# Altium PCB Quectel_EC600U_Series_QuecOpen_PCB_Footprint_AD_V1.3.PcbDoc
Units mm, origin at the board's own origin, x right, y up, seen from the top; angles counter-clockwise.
Board outline 152.4 x 101.6 mm, 2 copper layers (Top Layer, Bottom Layer); 1 components, 0 nets, 148 pads, 0 vias.
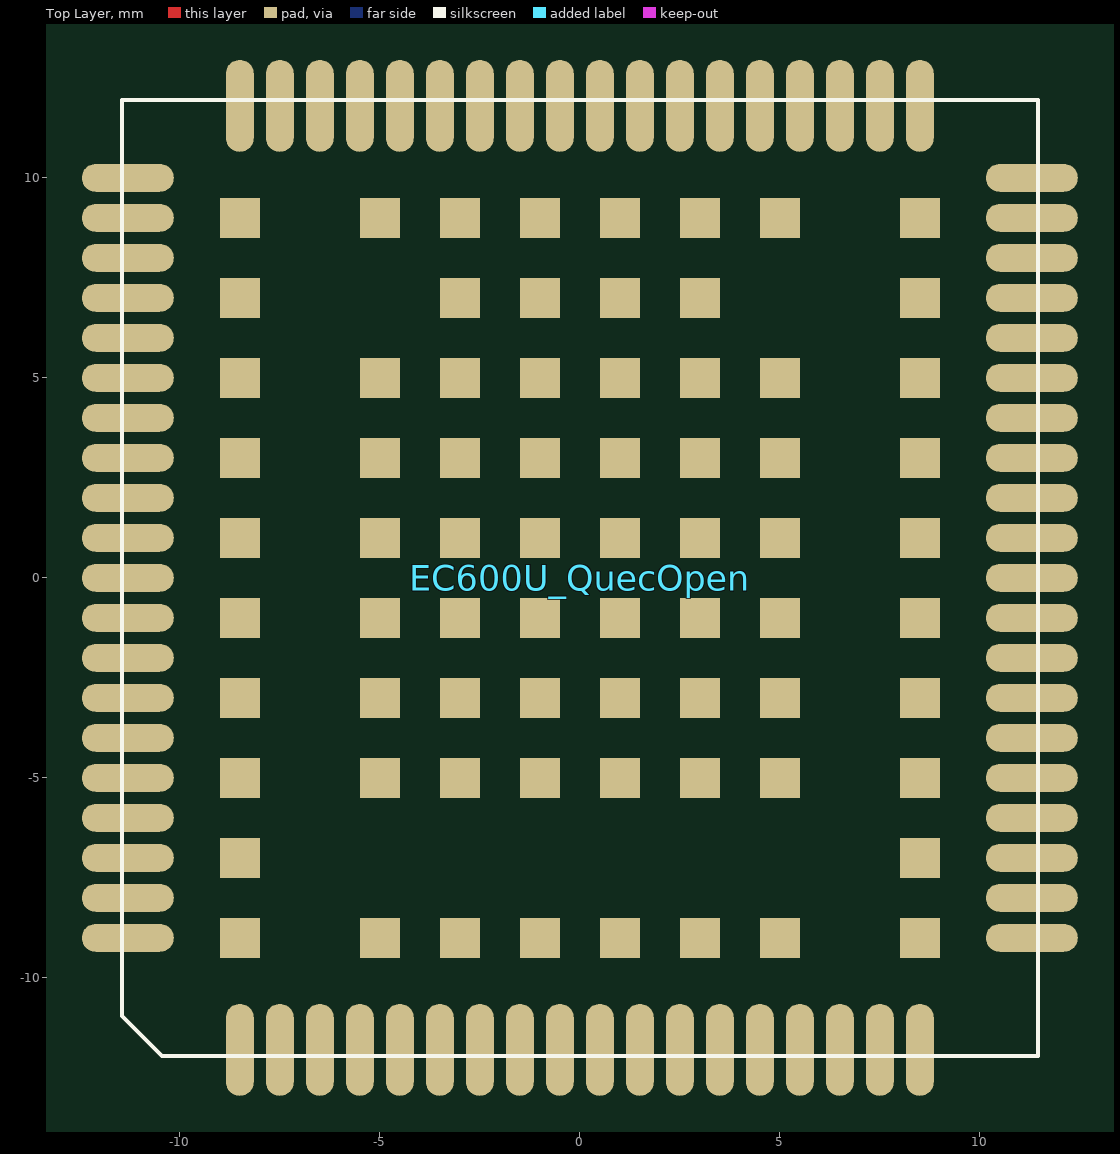
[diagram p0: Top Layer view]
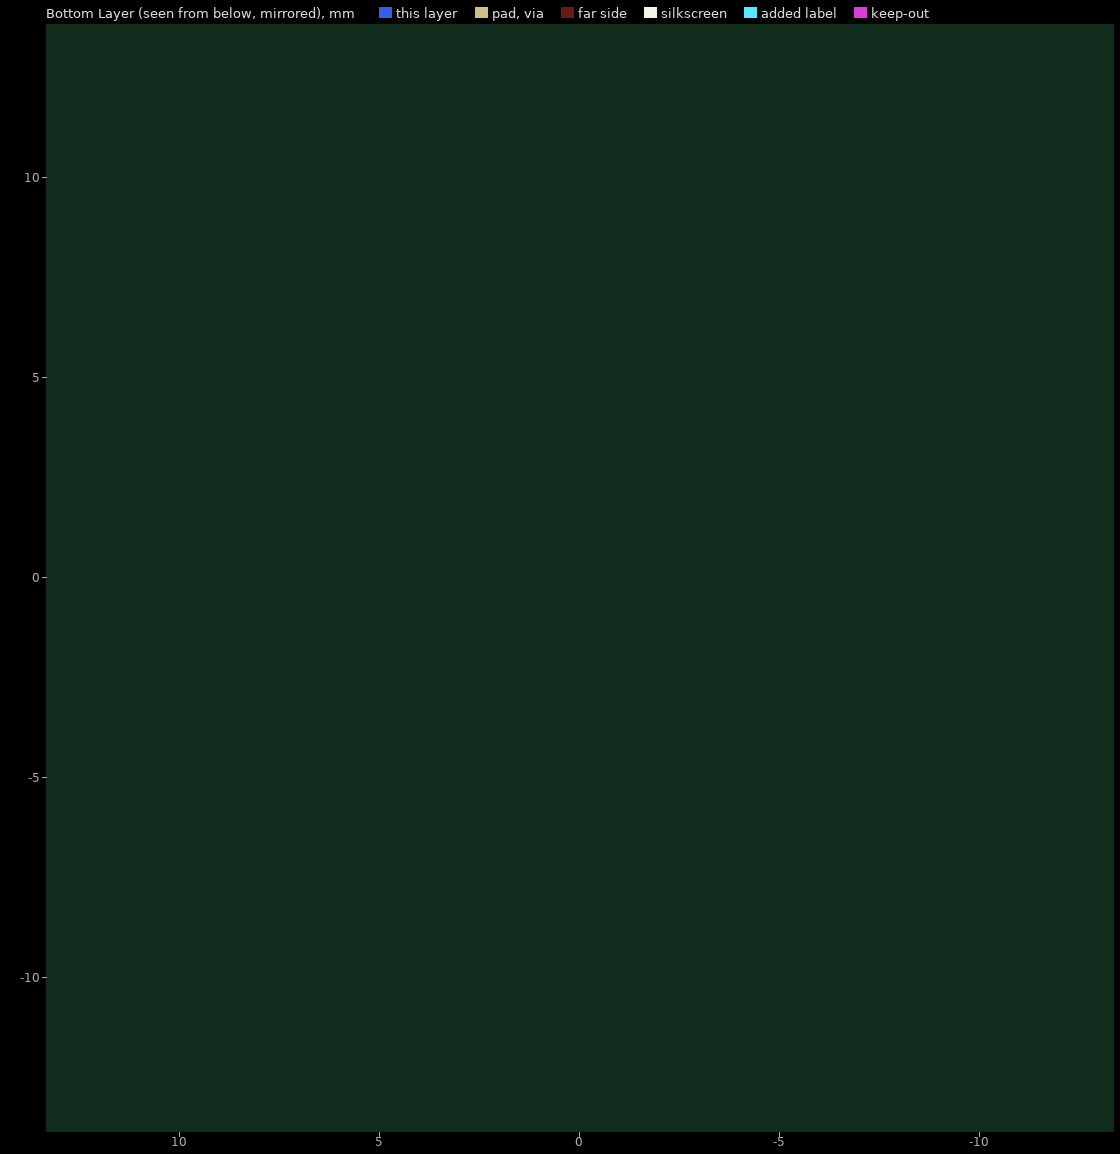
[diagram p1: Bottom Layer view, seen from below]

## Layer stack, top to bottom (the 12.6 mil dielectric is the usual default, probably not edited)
Top Solder: solder mask 0.0102, Solder Resist, Dk 3.5
Top Layer: signal copper 0.0356
Dielectric1: dielectric 0.32, FR-4, Dk 4.8
Bottom Layer: signal copper 0.0356
Bottom Solder: solder mask 0.0102, Solder Resist, Dk 3.5

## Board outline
-80.899,-52.07 71.501,-52.07 71.501,49.53 -80.899,49.53

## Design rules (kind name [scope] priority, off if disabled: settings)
Clearance [All] p1: gap=0.254
PolygonConnect [All] p1: connectstyle=Relief reliefconductorwidth=0.254 reliefentries=4 polygonreliefangle="90 Angle" airgapwidth=0.254
RoutingVias [All] p1: holewidth=0.711 width=1.27 viastyle="Through Hole" minholewidth=0.711 minwidth=1.27 maxholewidth=0.711 maxwidth=1.27
SolderMaskExpansion [All] p1: expansion=0.102
Width [All] p1: maxlimit=0.254 minlimit=0.254 preferedwidth=0.254
30 further rules are at their usual default settings.

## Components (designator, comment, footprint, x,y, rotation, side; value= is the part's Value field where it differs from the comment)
EC600U_QuecOpen "Comment" EC600U_QuecOpen 0,0 r0 top

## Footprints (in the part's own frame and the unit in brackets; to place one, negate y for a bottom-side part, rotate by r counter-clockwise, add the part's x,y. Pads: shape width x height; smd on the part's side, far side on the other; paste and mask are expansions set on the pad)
EC600U_QuecOpen [mm] "EC600U_QuecOpen Module LCC76PIN LGA72PIN H2.4mm RO"
  oval 0.7x2.3 smd mask+0.05: 1(-8.5,-11.8) 2(-7.5,-11.8) 3(-6.5,-11.8) 4(-5.5,-11.8) 5(-4.5,-11.8) 6(-3.5,-11.8) 7(-2.5,-11.8) 8(-1.5,-11.8) 9(-0.5,-11.8) 10(0.5,-11.8) 11(1.5,-11.8) 12(2.5,-11.8) 13(3.5,-11.8) 14(4.5,-11.8) 15(5.5,-11.8) 16(6.5,-11.8) 17(7.5,-11.8) 18(8.5,-11.8) 39(8.5,11.8) 40(7.5,11.8) 41(6.5,11.8) 42(5.5,11.8) 43(4.5,11.8) 44(3.5,11.8) 45(2.5,11.8) 46(1.5,11.8) 47(0.5,11.8) 48(-0.5,11.8) 49(-1.5,11.8) 50(-2.5,11.8) 51(-3.5,11.8) 52(-4.5,11.8) 53(-5.5,11.8) 54(-6.5,11.8) 55(-7.5,11.8) 56(-8.5,11.8)
  oval 2.3x0.7 smd mask+0.05: 19(11.3,-9) 20(11.3,-8) 21(11.3,-7) 22(11.3,-6) 23(11.3,-5) 24(11.3,-4) 25(11.3,-3) 26(11.3,-2) 27(11.3,-1) 28(11.3,0) 29(11.3,1) 30(11.3,2) 31(11.3,3) 32(11.3,4) 33(11.3,5) 34(11.3,6) 35(11.3,7) 36(11.3,8) 37(11.3,9) 38(11.3,10) 57(-11.3,10) 58(-11.3,9) 59(-11.3,8) 60(-11.3,7) 61(-11.3,6) 62(-11.3,5) 63(-11.3,4) 64(-11.3,3) 65(-11.3,2) 66(-11.3,1) 67(-11.3,0) 68(-11.3,-1) 69(-11.3,-2) 70(-11.3,-3) 71(-11.3,-4) 72(-11.3,-5) 73(-11.3,-6) 74(-11.3,-7) 75(-11.3,-8) 76(-11.3,-9)
  rect 1x1 smd mask+0.05: 77(-3,-3) 78(-1,-3) 79(1,-3) 80(3,-3) 81(3,-1) 82(3,1) 83(3,3) 84(1,3) 85(-1,3) 86(-3,3) 87(-3,1) 88(-3,-1) 89(-1,-1) 90(1,-1) 91(1,1) 92(-1,1) 93(-5,-5) 94(-3,-5) 95(-1,-5) 96(1,-5) 97(3,-5) 98(5,-5) 99(5,-3) 100(5,-1) 101(5,1) 102(5,3) 103(5,5) 104(3,5) 105(1,5) 106(-1,5) 107(-3,5) 108(-5,5) 109(-5,3) 110(-5,1) 111(-5,-1) 112(-5,-3) 113(-8.5,-9) 114(-5,-9) 115(-3,-9) 116(-1,-9) 117(1,-9) 118(3,-9) 119(5,-9) 120(8.5,-9) 121(8.5,-7) 122(8.5,-5) 123(8.5,-3) 124(8.5,-1) 125(8.5,1) 126(8.5,3) 127(8.5,5) 128(8.5,7) 129(8.5,9) 130(5,9) 131(3,9) 132(1,9) 133(-1,9) 134(-3,9) 135(-5,9) 136(-8.5,9) 137(-8.5,7) 138(-8.5,5) 139(-8.5,3) 140(-8.5,1) 141(-8.5,-1) 142(-8.5,-3) 143(-8.5,-5) 144(-8.5,-7) 145(3,7) 146(1,7) 147(-1,7) 148(-3,7)
  silkscreen extent -11.45,-11.95 11.45,11.95

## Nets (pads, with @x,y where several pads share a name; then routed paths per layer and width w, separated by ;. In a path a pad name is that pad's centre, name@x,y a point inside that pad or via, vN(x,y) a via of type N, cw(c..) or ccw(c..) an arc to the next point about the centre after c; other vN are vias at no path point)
pads on no net: EC600U_QuecOpen.1 EC600U_QuecOpen.2 EC600U_QuecOpen.3 EC600U_QuecOpen.4 EC600U_QuecOpen.5 EC600U_QuecOpen.6 EC600U_QuecOpen.7 EC600U_QuecOpen.8 EC600U_QuecOpen.9 EC600U_QuecOpen.10 EC600U_QuecOpen.11 EC600U_QuecOpen.12 EC600U_QuecOpen.13 EC600U_QuecOpen.14 EC600U_QuecOpen.15 EC600U_QuecOpen.16 EC600U_QuecOpen.17 EC600U_QuecOpen.18 EC600U_QuecOpen.19 EC600U_QuecOpen.20 EC600U_QuecOpen.21 EC600U_QuecOpen.22 EC600U_QuecOpen.23 EC600U_QuecOpen.24 EC600U_QuecOpen.25 EC600U_QuecOpen.26 EC600U_QuecOpen.27 EC600U_QuecOpen.28 EC600U_QuecOpen.29 EC600U_QuecOpen.30 EC600U_QuecOpen.31 EC600U_QuecOpen.32 EC600U_QuecOpen.33 EC600U_QuecOpen.34 EC600U_QuecOpen.35 EC600U_QuecOpen.36 EC600U_QuecOpen.37 EC600U_QuecOpen.38 EC600U_QuecOpen.39 EC600U_QuecOpen.40 EC600U_QuecOpen.41 EC600U_QuecOpen.42 EC600U_QuecOpen.43 EC600U_QuecOpen.44 EC600U_QuecOpen.45 EC600U_QuecOpen.46 EC600U_QuecOpen.47 EC600U_QuecOpen.48 EC600U_QuecOpen.49 EC600U_QuecOpen.50 EC600U_QuecOpen.51 EC600U_QuecOpen.52 EC600U_QuecOpen.53 EC600U_QuecOpen.54 EC600U_QuecOpen.55 EC600U_QuecOpen.56 EC600U_QuecOpen.57 EC600U_QuecOpen.58 EC600U_QuecOpen.59 EC600U_QuecOpen.60 EC600U_QuecOpen.61 EC600U_QuecOpen.62 EC600U_QuecOpen.63 EC600U_QuecOpen.64 EC600U_QuecOpen.65 EC600U_QuecOpen.66 EC600U_QuecOpen.67 EC600U_QuecOpen.68 EC600U_QuecOpen.69 EC600U_QuecOpen.70 EC600U_QuecOpen.71 EC600U_QuecOpen.72 EC600U_QuecOpen.73 EC600U_QuecOpen.74 EC600U_QuecOpen.75 EC600U_QuecOpen.76 EC600U_QuecOpen.77 EC600U_QuecOpen.78 EC600U_QuecOpen.79 EC600U_QuecOpen.80 EC600U_QuecOpen.81 EC600U_QuecOpen.82 EC600U_QuecOpen.83 EC600U_QuecOpen.84 EC600U_QuecOpen.85 EC600U_QuecOpen.86 EC600U_QuecOpen.87 EC600U_QuecOpen.88 EC600U_QuecOpen.89 EC600U_QuecOpen.90 EC600U_QuecOpen.91 EC600U_QuecOpen.92 EC600U_QuecOpen.93 EC600U_QuecOpen.94 EC600U_QuecOpen.95 EC600U_QuecOpen.96 EC600U_QuecOpen.97 EC600U_QuecOpen.98 EC600U_QuecOpen.99 EC600U_QuecOpen.100 EC600U_QuecOpen.101 EC600U_QuecOpen.102 EC600U_QuecOpen.103 EC600U_QuecOpen.104 EC600U_QuecOpen.105 EC600U_QuecOpen.106 EC600U_QuecOpen.107 EC600U_QuecOpen.108 EC600U_QuecOpen.109 EC600U_QuecOpen.110 EC600U_QuecOpen.111 EC600U_QuecOpen.112 EC600U_QuecOpen.113 EC600U_QuecOpen.114 EC600U_QuecOpen.115 EC600U_QuecOpen.116 EC600U_QuecOpen.117 EC600U_QuecOpen.118 EC600U_QuecOpen.119 EC600U_QuecOpen.120 EC600U_QuecOpen.121 EC600U_QuecOpen.122 EC600U_QuecOpen.123 EC600U_QuecOpen.124 EC600U_QuecOpen.125 EC600U_QuecOpen.126 EC600U_QuecOpen.127 EC600U_QuecOpen.128 EC600U_QuecOpen.129 EC600U_QuecOpen.130 EC600U_QuecOpen.131 EC600U_QuecOpen.132 EC600U_QuecOpen.133 EC600U_QuecOpen.134 EC600U_QuecOpen.135 EC600U_QuecOpen.136 EC600U_QuecOpen.137 EC600U_QuecOpen.138 EC600U_QuecOpen.139 EC600U_QuecOpen.140 EC600U_QuecOpen.141 EC600U_QuecOpen.142 EC600U_QuecOpen.143 EC600U_QuecOpen.144 EC600U_QuecOpen.145 EC600U_QuecOpen.146 EC600U_QuecOpen.147 EC600U_QuecOpen.148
